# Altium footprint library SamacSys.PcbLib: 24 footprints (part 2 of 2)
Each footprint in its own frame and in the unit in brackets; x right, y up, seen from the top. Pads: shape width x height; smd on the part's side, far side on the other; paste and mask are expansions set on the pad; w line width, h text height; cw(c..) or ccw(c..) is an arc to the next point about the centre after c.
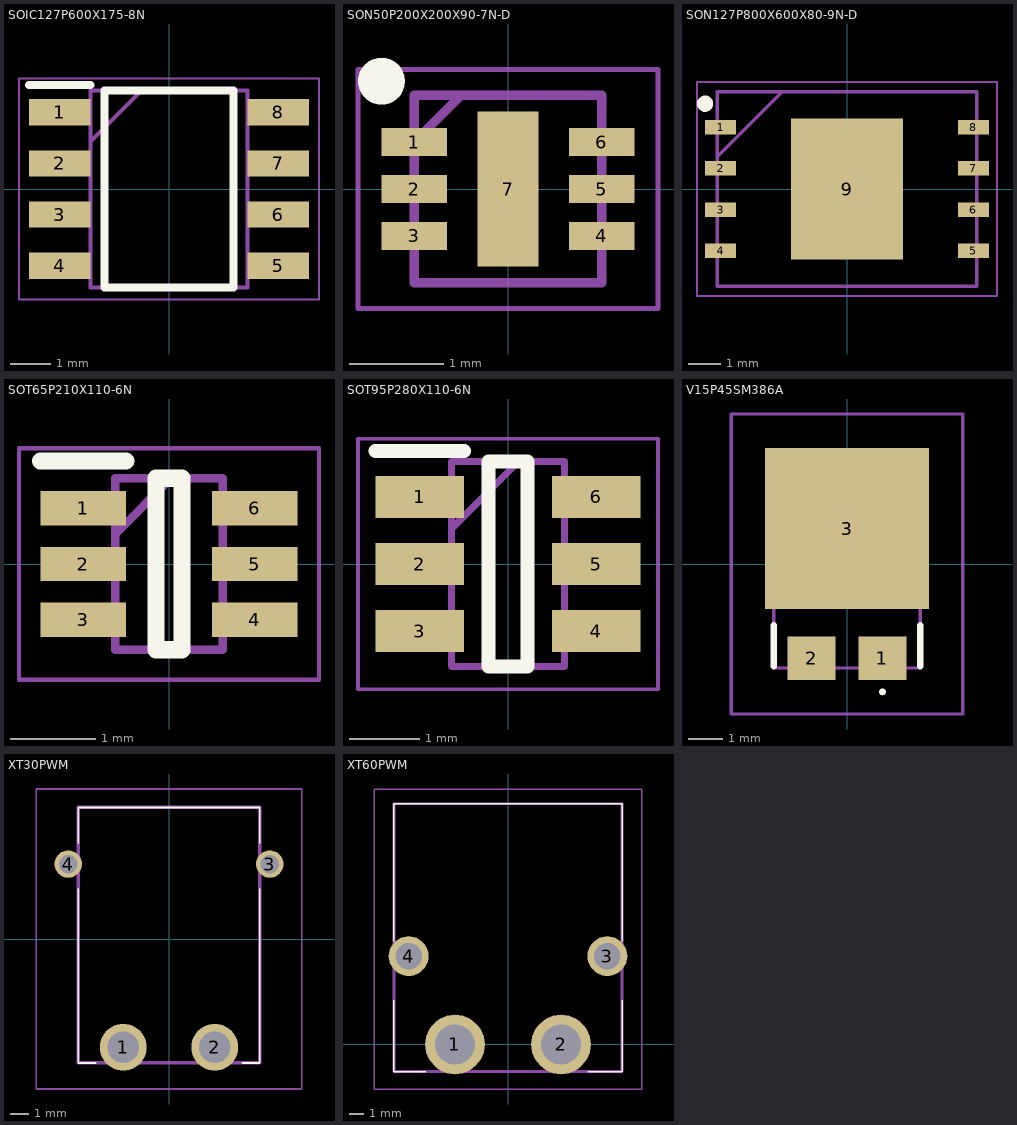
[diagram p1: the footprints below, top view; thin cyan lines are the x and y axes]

## SOIC127P600X175-8N [mm]
pads (8):
  rect 1.525x0.65 smd: 1(-2.712,1.905) 2(-2.712,0.635) 3(-2.712,-0.635) 4(-2.712,-1.905) 5(2.712,-1.905) 6(2.712,-0.635) 7(2.712,0.635) 8(2.712,1.905)
Top Overlay:
  lines w0.2: -3.475,2.58 -1.95,2.58 ; -1.6,-2.45 1.6,-2.45 1.6,2.45 -1.6,2.45 -1.6,-2.45
Mechanical 13:
  lines w0.1: -1.95,1.18 -0.68,2.45 ; -1.95,-2.45 1.95,-2.45 1.95,2.45 -1.95,2.45 -1.95,-2.45
Mechanical 15:
  lines w0.05: -3.725,-2.75 3.725,-2.75 3.725,2.75 -3.725,2.75 -3.725,-2.75
3D body "NE555DR.stp": height 1.75, standoff 0, extent -3,-2.45 3,2.45

## SON50P200X200X90-7N-D [mm]
pads (7):
  rect 0.7x0.3 smd: 1(-1,0.5) 2(-1,0) 3(-1,-0.5) 4(1,-0.5) 5(1,0) 6(1,0.5)
  rect 0.65x1.65 smd: 7(0,0)
Top Overlay:
  circle w0.25: c-1.35,1.15 r0.125
Mechanical 13:
  lines w0.1: -1,0.5 -0.5,1 ; -1,-1 -1,1 1,1 1,-1 -1,-1
Mechanical 15:
  lines w0.05: -1.6,-1.275 -1.6,1.275 1.6,1.275 1.6,-1.275 -1.6,-1.275
3D body "TQP4M0008.stp": height 0.85, standoff 0, extent -2.25,-2.25 2.25,2.25

## SON127P800X600X80-9N-D [mm]
pads (9):
  rect 0.95x0.45 smd: 1(-3.9,1.905) 2(-3.9,0.635) 3(-3.9,-0.635) 4(-3.9,-1.905) 5(3.9,-1.905) 6(3.9,-0.635) 7(3.9,0.635) 8(3.9,1.905)
  rect 3.45x4.35 smd: 9(0,0)
Top Overlay:
  circle w0.25: c-4.375,2.63 r0.125
Mechanical 13:
  lines w0.1: -4,1 -2,3 ; -4,-3 -4,3 4,3 4,-3 -4,-3
Mechanical 15:
  lines w0.05: -4.625,-3.3 -4.625,3.3 4.625,3.3 4.625,-3.3 -4.625,-3.3
3D body "W25Q01JVZEIM_TU.stp": height 0.8, standoff 0, extent -4.05,-3 4.05,3

## SOT65P210X110-6N [mm]
pads (6):
  rect 1x0.4 smd: 1(-1,0.65) 2(-1,0) 3(-1,-0.65) 4(1,-0.65) 5(1,0) 6(1,0.65)
Top Overlay:
  lines w0.2: -1.5,1.2 -0.5,1.2 ; -0.15,-1 -0.15,1 0.15,1 0.15,-1 -0.15,-1
Mechanical 13:
  lines w0.1: -0.625,0.35 0.025,1 ; -0.625,-1 -0.625,1 0.625,1 0.625,-1 -0.625,-1
Mechanical 15:
  lines w0.05: -1.75,-1.35 -1.75,1.35 1.75,1.35 1.75,-1.35 -1.75,-1.35
3D body "BZX84C3V3TS-7-F.stp": height 1.1, standoff 0, extent -1.05,-1 1.05,1

## SOT95P280X110-6N [mm]
pads (6):
  rect 1.25x0.6 smd: 1(-1.25,0.95) 2(-1.25,0) 3(-1.25,-0.95) 4(1.25,-0.95) 5(1.25,0) 6(1.25,0.95)
Top Overlay:
  lines w0.2: -1.875,1.6 -0.625,1.6 ; -0.275,-1.45 -0.275,1.45 0.275,1.45 0.275,-1.45 -0.275,-1.45
Mechanical 13:
  lines w0.1: -0.8,0.5 0.15,1.45 ; -0.8,-1.45 -0.8,1.45 0.8,1.45 0.8,-1.45 -0.8,-1.45
Mechanical 15:
  lines w0.05: -2.125,-1.775 -2.125,1.775 2.125,1.775 2.125,-1.775 -2.125,-1.775
3D body "LMR51430XDDCR.stp": height 0.97, standoff 0, extent -1.4,-1.45 1.4,1.45

## V15P45SM386A [mm]
pads (3):
  rect 1.4x1.27 smd: 1(1.04,-2.765) 2(-1.04,-2.765)
  rect 4.8x4.72 smd: 3(0,1.04)
Top Overlay:
  lines w0.1: 1.04,-3.8 ccw(c1.04,-3.75) 1.04,-3.7 ccw(c1.04,-3.75) 1.04,-3.8
  lines w0.2: -2.15,-3 -2.15,-1.8 ; 2.15,-3 2.15,-1.8
Mechanical 13:
  lines w0.1: -2.15,-3.05 -2.15,3.05 2.15,3.05 2.15,-3.05 -2.15,-3.05
Mechanical 15:
  lines w0.1: -3.4,-4.4 -3.4,4.4 3.4,4.4 3.4,-4.4 -3.4,-4.4
3D body "V15P45S-M3_86A.stp": height 1.3, standoff 0, extent -2.15,-3.273 2.15,3.05

## XT30PWM [mm]
pads (4):
  round 2.55 hole 1.7: 1(-2.5,-5.912) 2(2.5,-5.912)
  round 1.5 hole 1: 3(5.5,4.088) 4(-5.5,4.088)
Top Overlay:
  lines w0.1: -4.95,2.737 -4.95,-6.762 -4,-6.762 ; -4.95,5.237 -4.95,7.187 4.95,7.187 4.95,5.237 ; 4,-6.762 4.95,-6.762 4.95,2.737
Mechanical 13:
  lines w0.2: -4.95,-6.762 4.95,-6.762 4.95,7.187 -4.95,7.187 -4.95,-6.762
Mechanical 15:
  lines w0.1: -7.25,-8.188 7.25,-8.188 7.25,8.188 -7.25,8.188 -7.25,-8.188
3D body "XT30PW-M.stp": height 5.06, standoff -2.44, extent -6.65,-6.71 6.65,7.24

## XT60PWM [mm]
pads (4):
  round 4.05 hole 2.7: 1(-3.6,0) 2(3.6,0)
  round 2.7 hole 1.8: 3(6.75,6) 4(-6.75,6)
Top Overlay:
  lines w0.1: -7.75,3 -7.75,-1.85 -5.6,-1.85 ; -7.75,7 -7.75,16.35 7.75,16.35 7.75,7 ; 5.4,-1.85 7.75,-1.85 7.75,3
Mechanical 13:
  lines w0.2: -7.75,-1.85 -7.75,16.35 7.75,16.35 7.75,-1.85 -7.75,-1.85
Mechanical 15:
  lines w0.1: -9.1,-3.025 -9.1,17.35 9.1,17.35 9.1,-3.025 -9.1,-3.025
3D body "XT60PW-M.stp": height 8.44, standoff -2.51, extent -7.95,-1.98 7.95,16.298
